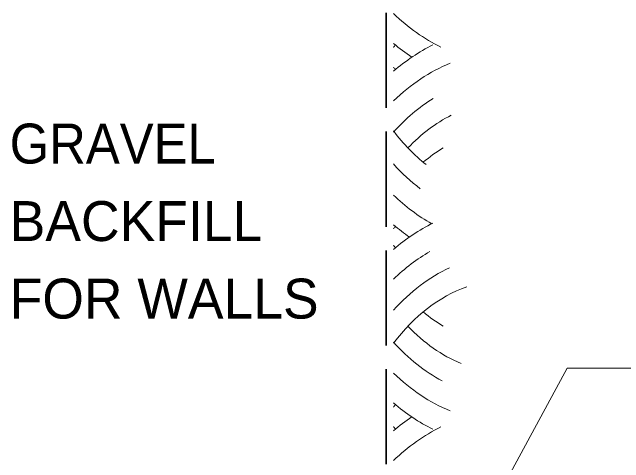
# Model space of a CAD drawing. Extents: x 17672 to 18472, y -9785 to -9267.
# Drawn here: x 18130.6 to 18184.5, y -9369.5 to -9329.6 of the extents above; entities that cross this region are included whole.
import ezdxf

# ---------------------------------------------------------------- set-up
doc = ezdxf.new("R2010")
doc.units = 0
doc.header["$LTSCALE"] = 1.4
doc.linetypes.add('LONG_DASHED', pattern=[7.5, 6, -1.5])
for name, color, linetype, lineweight in [('1', 7, 'Continuous', 13), ('15', 7, 'Continuous', 13), ('20', 7, 'Continuous', 25)]:
    doc.layers.add(name, color=color, linetype=linetype, lineweight=lineweight)

msp = doc.modelspace()

# ---------------------------------------------------------------- linework, layer by layer
at = {"layer": '1', "linetype": 'LONG_DASHED', "lineweight": 35}
msp.add_line((18163.555, -9390.594), (18163.555, -9317.655), dxfattribs=at)
at = {"layer": '1'}
for centre, major_axis, start_param, end_param in [((18174.22, -9309.631), (0, -24.471), 5.678359, 5.946281), ((18174.22, -9309.631), (0, -26.675), 5.734425, 5.830081), ((18174.22, -9357.608), (0, 26.675), 0.347284, 0.54876), ((18150.469, -9311.65), (0, -28.469), 0.735703, 0.74718), ((18174.22, -9357.608), (0, 24.471), 0.28844, 0.604826), ((18150.469, -9355.59), (0, 28.469), 5.536005, 5.547483), ((18174.22, -9357.608), (0, 22.266), 0.419017, 0.675019), ((18174.22, -9357.608), (0, 20.062), 0.347048, 0.649981), ((18174.22, -9325.666), (0, -20.062), 5.517669, 5.766375), ((18174.29, -9360.073), (0, 20.062), 0.405446, 0.543163), ((18174.22, -9325.666), (0, -22.266), 5.608166, 5.786033), ((18174.22, -9325.666), (0, -24.471), 5.678359, 5.89692), ((18174.22, -9373.356), (0, 26.675), 0.346641, 0.54876), ((18174.22, -9325.666), (0, -26.675), 5.734425, 5.819072), ((18150.469, -9327.684), (0, -28.469), 0.735703, 0.74718), ((18150.469, -9371.337), (0, 28.469), 5.536005, 5.547483), ((18174.22, -9373.356), (0, 24.471), 0.396562, 0.604826), ((18174.22, -9373.356), (0, 22.266), 0.321019, 0.675019), ((18174.22, -9373.356), (0, 20.062), 0.247668, 0.765516), ((18174.29, -9338.949), (0, -20.062), 5.740022, 5.87774), ((18174.22, -9341.413), (0, -20.062), 5.633205, 5.999911), ((18174.22, -9341.413), (0, -22.266), 5.608166, 5.918958), ((18174.22, -9341.413), (0, -24.471), 5.678359, 5.994746), ((18174.22, -9341.413), (0, -26.675), 5.734425, 5.935901), ((18150.469, -9343.432), (0, -28.469), 0.735703, 0.74718), ((18174.22, -9389.391), (0, 26.675), 0.453104, 0.54876), ((18174.22, -9389.391), (0, 24.471), 0.336904, 0.604826), ((18150.469, -9387.372), (0, 28.469), 5.536005, 5.547483)]:
    msp.add_ellipse(centre, major_axis=major_axis, ratio=0.719298, start_param=start_param, end_param=end_param, dxfattribs=at)
at = {"layer": '15'}
for q in [(18163.555, -9390.594), (18188.425, -9361.099)]:
    msp.add_line((18179.55, -9361.099), q, dxfattribs=at)

# ---------------------------------------------------------------- texts
at = {"layer": '20', "width": 0.95}
msp.add_text('GRAVEL', height=3.529, dxfattribs=at).set_placement((18130.337, -9343.011))
at = {"layer": '20'}
for s, p in [('BACKFILL', (18130.337, -9349.861)), ('FOR WALLS', (18130.337, -9356.712))]:
    msp.add_text(s, height=3.529, dxfattribs=at).set_placement(p)

doc.saveas('drawing.dxf')
